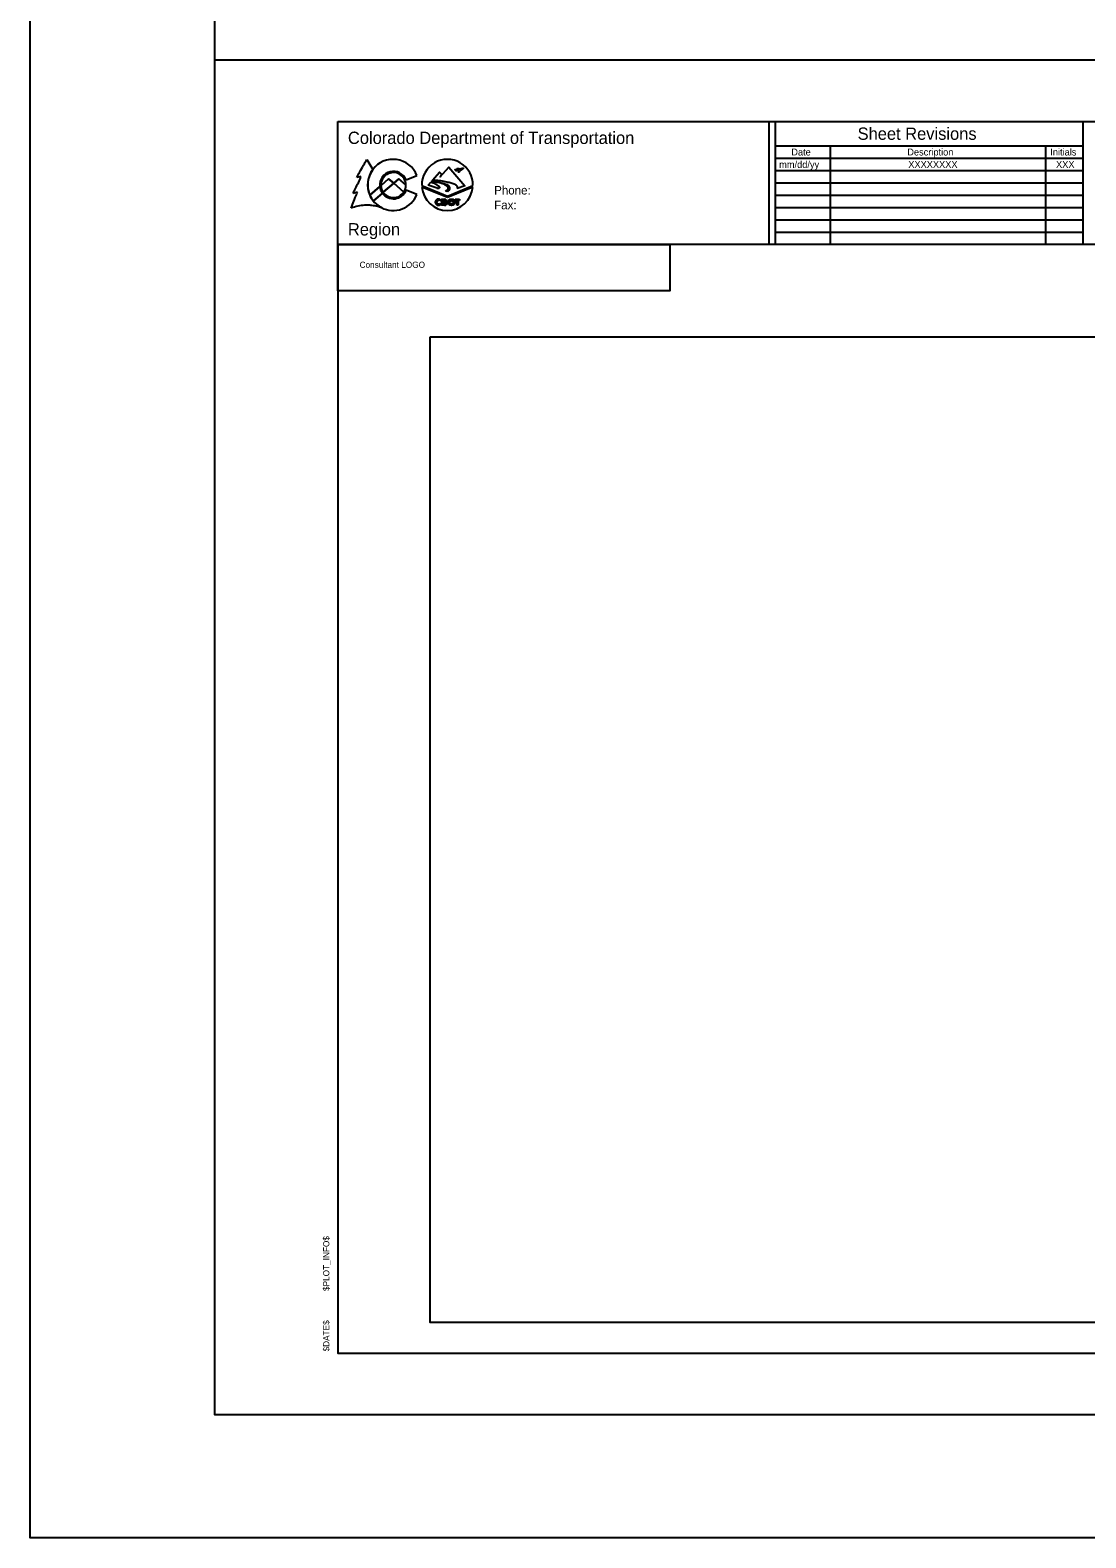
# Model space of a CAD drawing. Extents: x 0 to 3, y 0 to 2.
# Drawn here: x 0 to 0.715, y 0 to 1.02 of the extents above; entities that cross this region are included whole.
import ezdxf

# ---------------------------------------------------------------- set-up
doc = ezdxf.new("R2010")
doc.units = 0
for name, color, linetype in [('DRAFT_Information-No Plot', 7, 'Continuous'), ('SHEET_Lines', 7, 'Continuous'), ('SHEET_North Arrow', 7, 'Continuous'), ('SHEET_Plot Boundary', 7, 'Continuous'), ('SHEET_Text-Border Info', 7, 'Continuous')]:
    doc.layers.add(name, color=color, linetype=linetype)

msp = doc.modelspace()

# ---------------------------------------------------------------- linework, layer by layer
at = {"layer": 'DRAFT_Information-No Plot'}
msp.add_line((0.2083, 0.875), (0.2083, 0.875), dxfattribs=at)
msp.add_lwpolyline([(0.2708, 0.8125), (1.4375, 0.8125), (1.4375, 0.1458), (0.2708, 0.1458)], close=True, dxfattribs=at)
at = {"layer": 'SHEET_Lines'}
for p, q in [((0.125, 1), (2.9583, 1)), ((0.2083, 0.875), (0.2083, 0.9583)), ((0.2083, 0.9583), (1.5, 0.9583)), ((0.5, 0.9583), (0.5, 0.875)), ((0.5042, 0.9583), (0.5042, 0.875)), ((0.7125, 0.9583), (0.7125, 0.875)), ((0.5042, 0.9417), (0.7125, 0.9417)), ((0.5417, 0.875), (0.5417, 0.9417)), ((0.6875, 0.875), (0.6875, 0.9417)), ((0.5042, 0.9333), (0.7125, 0.9333)), ((0.5042, 0.925), (0.7125, 0.925)), ((0.5042, 0.9167), (0.7125, 0.9167)), ((0.5042, 0.9083), (0.7125, 0.9083)), ((0.5042, 0.9), (0.7125, 0.9)), ((0.5042, 0.8917), (0.7125, 0.8917)), ((0.5042, 0.8833), (0.7125, 0.8833))]:
    msp.add_line(p, q, dxfattribs=at)
for points in [[(2.9583, 0.0833), (0.125, 0.0833), (0.125, 1.9167), (2.9583, 1.9167)], [(0.2083, 0.875), (0.4329, 0.875), (0.4329, 0.8436), (0.2083, 0.8436)]]:
    msp.add_lwpolyline(points, close=True, dxfattribs=at)
msp.add_lwpolyline([(1.1375, 0.875), (0.2083, 0.875), (0.2083, 0.125), (1.5, 0.125), (1.5, 0.875), (1.275, 0.875)], dxfattribs=at)
at = {"layer": 'SHEET_Plot Boundary'}
for p, q in [((0.228, 0.9326), (0.232, 0.9258)), ((0.2239, 0.921), (0.2212, 0.9204)), ((0.2426, 0.9195), (0.2375, 0.915)), ((0.2375, 0.9149), (0.2426, 0.9194)), ((0.2461, 0.9165), (0.2426, 0.9195)), ((0.2426, 0.9194), (0.2461, 0.9164)), ((0.2496, 0.9195), (0.2461, 0.9165)), ((0.2461, 0.9164), (0.2496, 0.9194)), ((0.2544, 0.9153), (0.2496, 0.9195)), ((0.2496, 0.9194), (0.2544, 0.9152)), ((0.2545, 0.9188), (0.2618, 0.9217)), ((0.2717, 0.9178), (0.2719, 0.918)), ((0.2904, 0.9251), (0.2889, 0.9248)), ((0.2215, 0.9103), (0.2187, 0.9094)), ((0.2299, 0.9084), (0.2367, 0.9143)), ((0.2367, 0.9143), (0.2299, 0.9084)), ((0.2384, 0.9098), (0.2322, 0.9044)), ((0.2322, 0.9044), (0.2384, 0.9098)), ((0.2461, 0.9165), (0.239, 0.9103)), ((0.239, 0.9103), (0.2461, 0.9165)), ((0.253, 0.9105), (0.2461, 0.9165)), ((0.2461, 0.9165), (0.253, 0.9105)), ((0.2618, 0.9088), (0.2545, 0.9118)), ((0.2651, 0.9148), (0.2824, 0.9077)), ((0.2824, 0.9068), (0.2651, 0.9138)), ((0.2694, 0.9152), (0.2712, 0.9172)), ((0.2755, 0.913), (0.2694, 0.9152)), ((0.2814, 0.911), (0.2811, 0.9111)), ((0.2825, 0.9106), (0.2822, 0.9108)), ((0.2824, 0.9077), (0.2997, 0.9148)), ((0.2996, 0.9138), (0.2824, 0.9068)), ((0.2771, 0.9028), (0.2779, 0.9021)), ((0.2779, 0.905), (0.2772, 0.9043)), ((0.2878, 0.9047), (0.2878, 0.9056)), ((0.2878, 0.9056), (0.2907, 0.9056)), ((0.2888, 0.9047), (0.2878, 0.9047)), ((0.2888, 0.9015), (0.2888, 0.9047)), ((0.2897, 0.9015), (0.2888, 0.9015)), ((0.2907, 0.9047), (0.2897, 0.9047)), ((0.2897, 0.9047), (0.2897, 0.9015)), ((0.2907, 0.9056), (0.2907, 0.9047))]:
    msp.add_line(p, q, dxfattribs=at)
msp.add_lwpolyline([(0, 2), (3, 2), (3, 0), (0, 0)], close=True, dxfattribs=at)
for points in [[(0.2724, 0.9186), (0.2771, 0.924), (0.2785, 0.9226), (0.2775, 0.9208), (0.2834, 0.9274), (0.2942, 0.9146), (0.2891, 0.9129)], [(0.2805, 0.9015), (0.2787, 0.9015), (0.2787, 0.9056), (0.2805, 0.9056)], [(0.2803, 0.9047), (0.2797, 0.9047), (0.2797, 0.9023), (0.2803, 0.9023)]]:
    msp.add_lwpolyline(points, dxfattribs=at)
for radius in [0.00212, 0.00114]:
    msp.add_circle((0.2852, 0.9036), radius, dxfattribs=at)
for centre, radius, start, end in [((0.2457, 0.9153), 0.0173, 21.7587, 203.3886), ((0.2824, 0.9153), 0.0173, 358.517, 181.483), ((0.2458, 0.9153), 0.0173, 142.5902, 242.6738), ((0.2459, 0.9152), 0.00928, 22.3606, 185.6203), ((0.2459, 0.9152), 0.00845, 0.3586, 181.561), ((0.2457, 0.9153), 0.0173, 203.3886, 242.7191), ((0.2459, 0.9152), 0.00928, 185.6203, 215.8725), ((0.2459, 0.9152), 0.00845, 181.561, 215.3766), ((0.2457, 0.9153), 0.0173, 242.7191, 338.2684), ((0.2459, 0.9152), 0.00928, 215.8725, 338.0486), ((0.2459, 0.9152), 0.00845, 215.3766, 326.2328), ((0.2459, 0.9152), 0.00845, 326.2328, 0.3586), ((0.2824, 0.9153), 0.0173, 184.8402, 355.1598), ((0.2458, 0.9153), 0.0173, 218.6779, 242.6738), ((0.2458, 0.9153), 0.0173, 218.6779, 242.6738), ((0.2763, 0.9036), 0.00212, 42.6236, 316.6779), ((0.2763, 0.9036), 0.00114, 42.6236, 316.6779), ((0.2802, 0.9035), 0.00118, 273.2236, 86.7764), ((0.2803, 0.9035), 0.00207, 276.249, 83.751)]:
    msp.add_arc(centre, radius, start, end, dxfattribs=at)
for points in [[(0.2212, 0.9204), (0.223, 0.9238), (0.2257, 0.9286), (0.228, 0.9326)], [(0.2187, 0.9094), (0.2197, 0.9119), (0.2235, 0.9198), (0.2239, 0.921)], [(0.2719, 0.918), (0.2764, 0.9171), (0.2804, 0.9159), (0.2821, 0.9152), (0.2831, 0.9144), (0.2838, 0.9134), (0.2834, 0.9116), (0.2825, 0.9106)], [(0.2891, 0.9129), (0.2893, 0.9135), (0.289, 0.9145), (0.2871, 0.9157), (0.2843, 0.9167), (0.2812, 0.9173), (0.2789, 0.9178), (0.275, 0.9183), (0.2724, 0.9186)], [(0.2889, 0.9248), (0.2884, 0.9248), (0.2883, 0.9248), (0.2881, 0.9251), (0.2877, 0.9256), (0.2877, 0.9257), (0.2879, 0.9258), (0.2882, 0.9257), (0.2884, 0.9256), (0.2888, 0.9254), (0.2889, 0.9254), (0.289, 0.9254), (0.29, 0.9257)], [(0.29, 0.9257), (0.2894, 0.926), (0.2892, 0.9261), (0.289, 0.9262), (0.2891, 0.9263), (0.2894, 0.9264), (0.2896, 0.9265), (0.2898, 0.9265), (0.29, 0.9264), (0.2904, 0.9263), (0.291, 0.9261)], [(0.2915, 0.9254), (0.2909, 0.9246), (0.2905, 0.9241), (0.2902, 0.9239), (0.2899, 0.9239), (0.2901, 0.9244), (0.2904, 0.9251)], [(0.291, 0.9261), (0.2917, 0.9264), (0.2924, 0.9266), (0.2926, 0.9267), (0.2929, 0.9267), (0.2931, 0.9267), (0.2932, 0.9266), (0.2932, 0.9264), (0.293, 0.9262), (0.2924, 0.9258), (0.2915, 0.9254)], [(0.2173, 0.8996), (0.2182, 0.902), (0.2201, 0.9067), (0.2215, 0.9103)], [(0.2712, 0.9172), (0.272, 0.917), (0.2726, 0.9168), (0.2737, 0.9164), (0.2748, 0.9157), (0.2758, 0.9151), (0.2763, 0.9147), (0.2768, 0.9141), (0.277, 0.9138), (0.277, 0.9136), (0.2769, 0.9132), (0.2767, 0.913), (0.2765, 0.9129), (0.2761, 0.9128), (0.2759, 0.9129), (0.2757, 0.9129), (0.2755, 0.913)], [(0.2802, 0.9157), (0.2805, 0.9156), (0.2808, 0.9154), (0.2811, 0.9153), (0.2812, 0.9152), (0.2813, 0.9151), (0.2815, 0.915), (0.2817, 0.9149), (0.2819, 0.9147), (0.282, 0.9146), (0.2821, 0.9146), (0.2822, 0.9145), (0.2823, 0.9143), (0.2825, 0.9142), (0.2826, 0.914), (0.2827, 0.9139), (0.2827, 0.9138), (0.2828, 0.9137), (0.2828, 0.9136), (0.2828, 0.9135), (0.2828, 0.9134), (0.2829, 0.9133), (0.2829, 0.913), (0.2828, 0.9127), (0.2828, 0.9126), (0.2827, 0.9124), (0.2826, 0.9122), (0.2824, 0.9119), (0.2822, 0.9117), (0.282, 0.9115), (0.2818, 0.9114), (0.2817, 0.9112), (0.2816, 0.9111), (0.2814, 0.911)], [(0.2822, 0.9108), (0.2827, 0.9112), (0.2833, 0.9119), (0.2835, 0.9123), (0.2834, 0.9136), (0.2832, 0.9139), (0.2827, 0.9143), (0.2814, 0.9152), (0.2802, 0.9157)], [(0.2378, 0.8999), (0.2353, 0.9006), (0.2313, 0.9014), (0.2284, 0.9016), (0.2263, 0.9015), (0.2217, 0.9009), (0.2173, 0.8996)]]:
    msp.add_spline(points, degree=3, dxfattribs=at)
msp.add_open_spline([(0.2811, 0.9111), (0.2857, 0.9143), (0.2785, 0.9165), (0.2717, 0.9178)], degree=2, dxfattribs=at)

# ---------------------------------------------------------------- texts
at = {"layer": 'DRAFT_Information-No Plot'}
msp.add_text('Consultant LOGO', height=0.004167, dxfattribs=at).set_placement((0.223, 0.8592))
at = {"layer": 'SHEET_North Arrow'}
for s, height, p in [('Colorado Department of Transportation', 0.008333, (0.2151, 0.943)), ('Sheet Revisions', 0.008333, (0.5601, 0.9458)), ('Region ', 0.00833, (0.2151, 0.8811))]:
    msp.add_text(s, height=height, dxfattribs=at).set_placement(p)
at = {"layer": 'SHEET_Text-Border Info'}
for s, height, p in [('Date', 0.00467, (0.5152, 0.9352)), ('Description', 0.004667, (0.5937, 0.9352)), ('Initials', 0.00467, (0.6905, 0.9352)), ('mm/dd/yy', 0.00467, (0.507, 0.9268)), ('XXXXXXXX', 0.00467, (0.5944, 0.9268)), ('XXX', 0.00467, (0.6944, 0.9268)), ('Phone:', 0.00583, (0.3141, 0.9088)), ('Fax:', 0.00583, (0.3141, 0.8988))]:
    msp.add_text(s, height=height, dxfattribs=at).set_placement(p)
for s, height, p in [('$PLOT_INFO$', 0.004167, (0.2025, 0.167)), ('$PLOT_INFO$', 0.004167, (0.2025, 0.167)), ('$DATE$', 0.00417, (0.2025, 0.1261)), ('$DATE$', 0.00417, (0.2025, 0.1261))]:
    msp.add_text(s, height=height, rotation=90, dxfattribs=at).set_placement(p)

doc.saveas('drawing.dxf')
